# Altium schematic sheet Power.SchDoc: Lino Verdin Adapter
size A3; Organization: Toradex AG; Address1: Ebenaustrasse 10; Address2: Horw; Address3: 6048; Address4: Switzerland; DocumentNumber: 3; Revision: V1.1; SheetNumber: 3; SheetTotal: 8; PageSetup: Record=PageOptions¦CenterHorizontal=True¦CenterVertical=True¦PrintScale=0.73¦XCorrection=1.00¦YCorrection=1.00¦PrintKind=0¦BorderSize=5000000¦LeftOffset=0¦BottomOffset=0¦Orientation=2¦PaperLength=1000¦PaperWidth=1000¦Scale=100¦PaperSource=7¦PrintQuality=-4¦MediaType=1¦DitherType=10¦PaperKind=A4¦PrintScaleMode=1
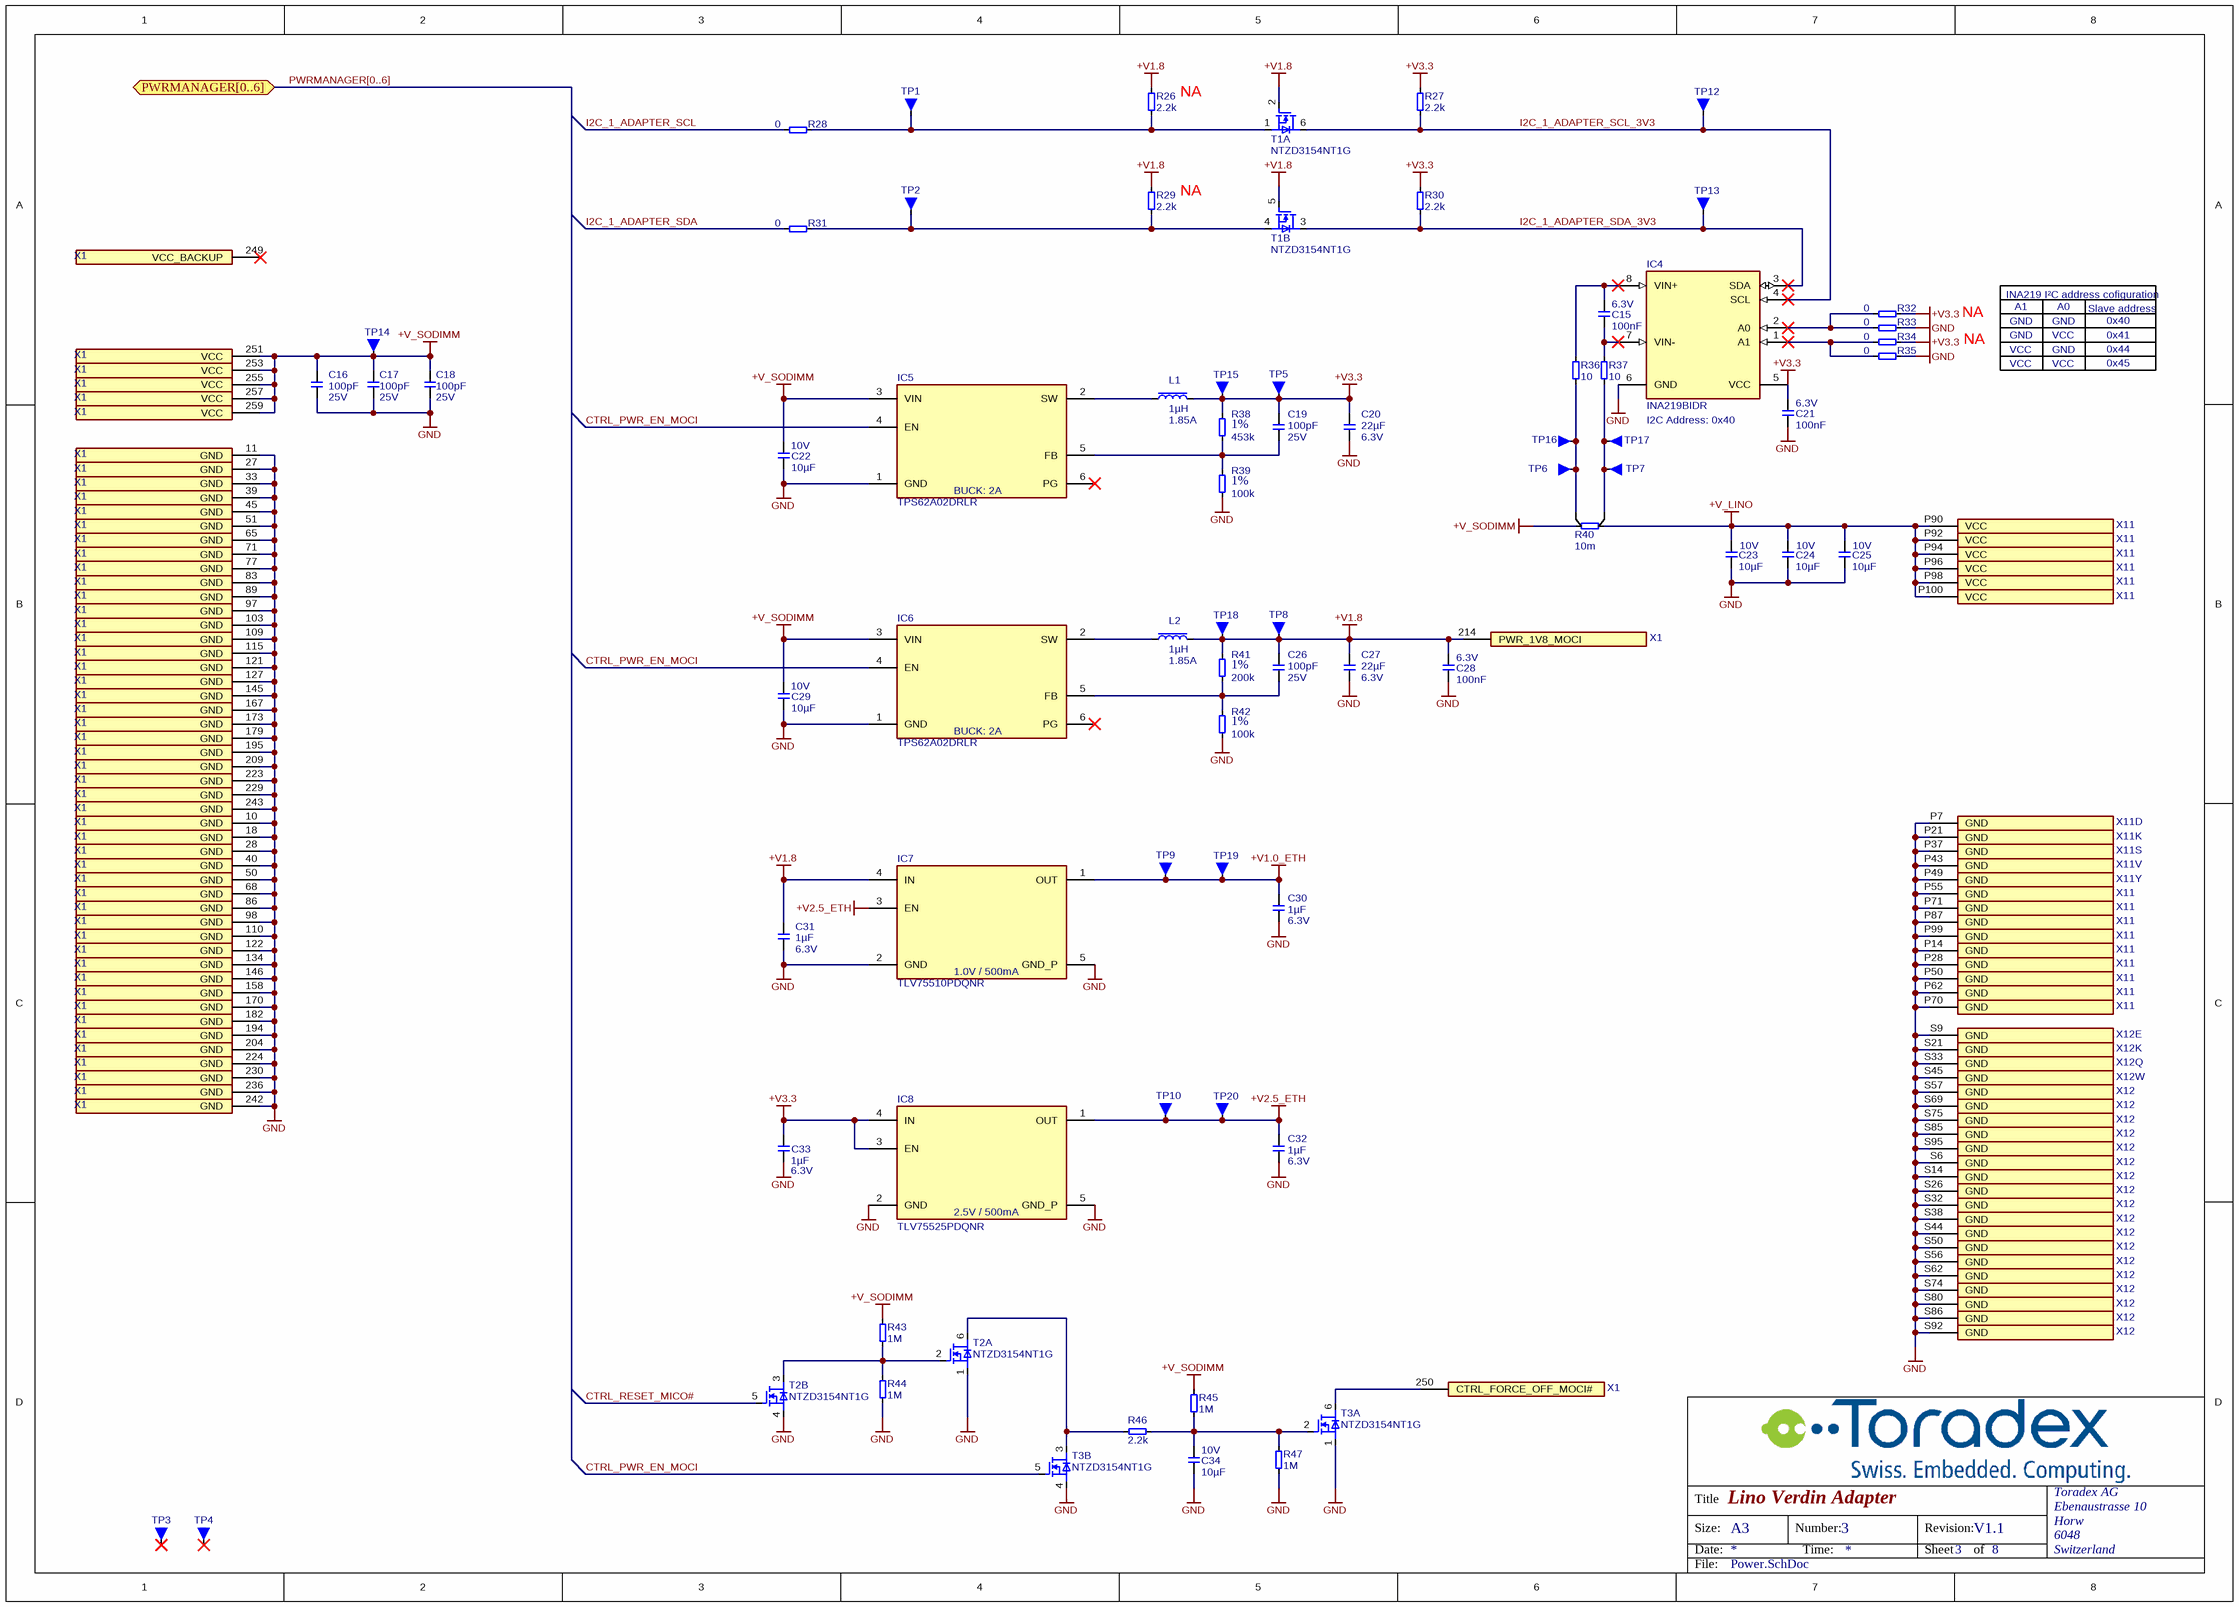
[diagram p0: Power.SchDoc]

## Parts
C15  value 100nF  Rating: 6.3V  [CAPC60X30X33L15L]  (hidden comment: C-X5R-100n-6.3V-10%-0201)
C16  value 100pF  Rating: 25V  [CAPC60X30X33L15L]  (hidden comment: C-NP0-100p-25V-5%-0201)
C17  value 100pF  Rating: 25V  [CAPC60X30X33L15L]  (hidden comment: C-NP0-100p-25V-5%-0201)
C18  value 100pF  Rating: 25V  [CAPC60X30X33L15L]  (hidden comment: C-NP0-100p-25V-5%-0201)
C19  value 100pF  Rating: 25V  [CAPC60X30X33L15L]  (hidden comment: C-NP0-100p-25V-5%-0201)
C20  value 22µF  Rating: 6.3V  [CAPC200X125X100L50N]  (hidden comment: C-X5R-22u-6.3V-20%-0805)
C21  value 100nF  Rating: 6.3V  [CAPC60X30X33L15L]  (hidden comment: C-X5R-100n-6.3V-10%-0201)
C22  value 10µF  Rating: 10V  [CAPC160X80X90L35N]  (hidden comment: C-X5R-10u-10V-20%-0603)
C23  value 10µF  Rating: 10V  [CAPC160X80X90L35N]  (hidden comment: C-X5R-10u-10V-20%-0603)
C24  value 10µF  Rating: 10V  [CAPC160X80X90L35N]  (hidden comment: C-X5R-10u-10V-20%-0603)
C25  value 10µF  Rating: 10V  [CAPC160X80X90L35N]  (hidden comment: C-X5R-10u-10V-20%-0603)
C26  value 100pF  Rating: 25V  [CAPC60X30X33L15L]  (hidden comment: C-NP0-100p-25V-5%-0201)
C27  value 22µF  Rating: 6.3V  [CAPC200X125X100L50N]  (hidden comment: C-X5R-22u-6.3V-20%-0805)
C28  value 100nF  Rating: 6.3V  [CAPC60X30X33L15L]  (hidden comment: C-X5R-100n-6.3V-10%-0201)
C29  value 10µF  Rating: 10V  [CAPC160X80X90L35N]  (hidden comment: C-X5R-10u-10V-20%-0603)
C30  value 1µF  Rating: 6.3V  [CAPC60X30X33L15L]  (hidden comment: C-X5R-1u-6.3V-20%-0201)
C31  value 1µF  Rating: 6.3V  [CAPC60X30X33L15L]  (hidden comment: C-X5R-1u-6.3V-20%-0201)
C32  value 1µF  Rating: 6.3V  [CAPC60X30X33L15L]  (hidden comment: C-X5R-1u-6.3V-20%-0201)
C33  value 1µF  Rating: 6.3V  [CAPC60X30X33L15L]  (hidden comment: C-X5R-1u-6.3V-20%-0201)
C34  value 10µF  Rating: 10V  [CAPC160X80X90L35N]  (hidden comment: C-X5R-10u-10V-20%-0603)
IC4  Manufacturer Part No.: INA219BIDR  [SOIC8P127_500X600X175L100X40_no_Silkscreen]  (hidden comment: IC-TI-INA219BIDR)
IC5  Manufacturer Part No.: TPS62A02DRLR  [SOT563-6P50_160X60L30N]  (hidden comment: TI-TPS62A02DRLR)
IC6  Manufacturer Part No.: TPS62A02DRLR  [SOT563-6P50_160X60L30N]  (hidden comment: TI-TPS62A02DRLR)
IC7  Manufacturer Part No.: TLV75510PDQNR  [X2SON4P65_100X100X40L36X21T48X48-1x1mm]  (hidden comment: IC-TI-TLV75510PDQNR)
IC8  Manufacturer Part No.: TLV75525PDQNR  [X2SON4P65_100X100X40L36X21T48X48-1x1mm]  (hidden comment: TI-TLV75525PDQNR)
L1  value 1µH  Rating: 1.85A  [INDC1008X40N]  (hidden comment: L-TAYIO-MBMK2520T1R0M)
L2  value 1µH  Rating: 1.85A  [INDC1008X40N]  (hidden comment: L-TAYIO-MBMK2520T1R0M)
R26  value 2.2k  [RESC60X30X33L15L]  (hidden comment: R-2.2K-50mW-5%-0201)
R27  value 2.2k  [RESC60X30X33L15L]  (hidden comment: R-2.2K-50mW-5%-0201)
R28  value 0  [RESC60X30X33L15L]  (hidden comment: R-0R-50mW-5%-0201)
R29  value 2.2k  [RESC60X30X33L15L]  (hidden comment: R-2.2K-50mW-5%-0201)
R30  value 2.2k  [RESC60X30X33L15L]  (hidden comment: R-2.2K-50mW-5%-0201)
R31  value 0  [RESC60X30X33L15L]  (hidden comment: R-0R-50mW-5%-0201)
R32  value 0  [RESC60X30X33L15L]  (hidden comment: R-0R-50mW-5%-0201)
R33  value 0  [RESC60X30X33L15L]  (hidden comment: R-0R-50mW-5%-0201)
R34  value 0  [RESC60X30X33L15L]  (hidden comment: R-0R-50mW-5%-0201)
R35  value 0  [RESC60X30X33L15L]  (hidden comment: R-0R-50mW-5%-0201)
R36  value 10  [RESC60X30X33L15L]  (hidden comment: R-10R-50mW-5%-0201)
R37  value 10  [RESC60X30X33L15L]  (hidden comment: R-10R-50mW-5%-0201)
R38  value 453k  Tolerance: 1%  [RESC60X30X33L15L]  (hidden comment: R-453K-50mW-1%-0201)
R39  value 100k  Tolerance: 1%  [RESC60X30X33L15L]  (hidden comment: R-100K-50mW-1%-0201)
R40  value 10m  [RESSC320X160X65L60N]  (hidden comment: R-VISHAY-WSK1206R0100FEA18)
R41  value 200k  Tolerance: 1%  [RESC60X30X33L15L]  (hidden comment: R-200K-50mW-1%-0201)
R42  value 100k  Tolerance: 1%  [RESC60X30X33L15L]  (hidden comment: R-100K-50mW-1%-0201)
R43  value 1M  [RESC60X30X33L15L]  (hidden comment: R-1M-50mW-5%-0201)
R44  value 1M  [RESC60X30X33L15L]  (hidden comment: R-1M-50mW-5%-0201)
R45  value 1M  [RESC60X30X33L15L]  (hidden comment: R-1M-50mW-5%-0201)
R46  value 2.2k  [RESC60X30X33L15L]  (hidden comment: R-2.2K-50mW-5%-0201)
R47  value 1M  [RESC60X30X33L15L]  (hidden comment: R-1M-50mW-5%-0201)
T1  Manufacturer Part No.: NTZD3154NT1G  [SOT563-6P50_160X60L30N]  (hidden comment: T-ONSEMI-NTZD3154NT1G)  (parts A,B of 2)
T2  Manufacturer Part No.: NTZD3154NT1G  [SOT563-6P50_160X60L30N]  (hidden comment: T-ONSEMI-NTZD3154NT1G)  (parts A,B of 2)
T3  Manufacturer Part No.: NTZD3154NT1G  [SOT563-6P50_160X60L30N]  (hidden comment: T-ONSEMI-NTZD3154NT1G)  (parts A,B of 2)
TP1  #TestPin_SMD-1.5x2.2mm#_NoPaste  [TESTPIN/2.20x1.50]  (value not drawn)  (no BOM)
TP2  #TestPin_SMD-1.5x2.2mm#_NoPaste  [TESTPIN/2.20x1.50]  (value not drawn)  (no BOM)
TP3  #TestPin_SMD-1.5x2.2mm#_NoPaste  [TESTPIN/2.20x1.50]  (value not drawn)  (no BOM)
TP4  #TestPin_SMD-1.5x2.2mm#_NoPaste  [TESTPIN/2.20x1.50]  (value not drawn)  (no BOM)
TP5  #TestPin_SMD-1.5x2.2mm#_NoPaste  [TESTPIN/2.20x1.50]  (value not drawn)  (no BOM)
TP6  #TestPin_SMD-1.5x2.2mm#_NoPaste  [TESTPIN/2.20x1.50]  (value not drawn)  (no BOM)
TP7  #TestPin_SMD-1.5x2.2mm#_NoPaste  [TESTPIN/2.20x1.50]  (value not drawn)  (no BOM)
TP8  #TestPin_SMD-1.5x2.2mm#_NoPaste  [TESTPIN/2.20x1.50]  (value not drawn)  (no BOM)
TP9  #TestPin_SMD-1.5x2.2mm#_NoPaste  [TESTPIN/2.20x1.50]  (value not drawn)  (no BOM)
TP10  #TestPin_SMD-1.5x2.2mm#_NoPaste  [TESTPIN/2.20x1.50]  (value not drawn)  (no BOM)
TP12  #TestPin_SMD-1.00mm#_NoPaste  [Pad_SMT_1.0x1.0_NoPaste]  (value not drawn)  (no BOM)
TP13  #TestPin_SMD-1.00mm#_NoPaste  [Pad_SMT_1.0x1.0_NoPaste]  (value not drawn)  (no BOM)
TP14  #TestPin_SMD-1.00mm#_NoPaste  [Pad_SMT_1.0x1.0_NoPaste]  (value not drawn)  (no BOM)
TP15  #TestPin_SMD-1.00mm#_NoPaste  [Pad_SMT_1.0x1.0_NoPaste]  (value not drawn)  (no BOM)
TP16  #TestPin_SMD-1.00mm#_NoPaste  [Pad_SMT_1.0x1.0_NoPaste]  (value not drawn)  (no BOM)
TP17  #TestPin_SMD-1.00mm#_NoPaste  [Pad_SMT_1.0x1.0_NoPaste]  (value not drawn)  (no BOM)
TP18  #TestPin_SMD-1.00mm#_NoPaste  [Pad_SMT_1.0x1.0_NoPaste]  (value not drawn)  (no BOM)
TP19  #TestPin_SMD-1.00mm#_NoPaste  [Pad_SMT_1.0x1.0_NoPaste]  (value not drawn)  (no BOM)
TP20  #TestPin_SMD-1.00mm#_NoPaste  [Pad_SMT_1.0x1.0_NoPaste]  (value not drawn)  (no BOM)
X1  CON-SODIMM-DDR4-TEST  [SODIMM_DDR4_no_Module]  (value not drawn)  (parts C,L,O,R,Z,31,39,42,45,48,51,57,60,63,66,69,73,76,81,84,87,96,106,109,112,120,127,133,136,143,146,147,148,149,150,151,156,159,164,170,175,183,192,198,204,209,215,221,227,233,238,244,249,254,259 of 260)  (no BOM)
X11  CON-LINO-P-CARRIER  [HIROSE_DF40C_100DS_LINO_CARRIER_PRIMARY]  (value not drawn)  (parts D,K,S,V,Y,28,36,44,50,57,64,75,81,85,95,96,97,98,99,100 of 100)
X12  CON-LINO-S-CARRIER  [HIROSE_DF40C_100DS_LINO_CARRIER_SECONDARY]  (value not drawn)  (parts E,K,Q,W,29,35,38,43,48,53,57,63,66,69,72,75,78,81,87,90,93,96 of 100)

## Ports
PWRMANAGER[0..6] (bidir)

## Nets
+V1.0_ETH: C30.2 IC7.1(OUT) TP9.1 TP19.1
+V1.8: C26.2 C27.2 C28.2 C31.2 IC7.4(IN) L2.2 R26.2 R29.2 R41.2 T1.2(G) T1.5(G) TP8.1 TP18.1 X1.214(PWR_1V8_MOCI)
+V2.5_ETH: C32.2 IC7.3(EN) IC8.1(OUT) TP10.1 TP20.1
+V3.3: C19.2 C20.2 C21.2 C33.1 IC4.5(VCC) IC8.3(EN) IC8.4(IN) L1.2 R27.2 R30.2 R32.2 R34.2 R38.2 TP5.1 TP15.1
+V_LINO: C23.2 C24.2 C25.2 R40.1 X11.P90(VCC) X11.P92(VCC) X11.P94(VCC) X11.P96(VCC) X11.P98(VCC) X11.P100(VCC)
+V_SODIMM: C16.2 C17.2 C18.2 C22.2 C29.2 IC5.3(VIN) IC6.3(VIN) R40.4 R43.2 R45.2 TP14.1 X1.251(VCC) X1.253(VCC) X1.255(VCC) X1.257(VCC) X1.259(VCC)
GND: C16.1 C17.1 C18.1 C20.1 C21.1 C22.1 C23.1 C24.1 C25.1 C27.1 C28.1 C29.1 C30.1 C31.1 C32.1 C33.2 C34.1 IC4.6(GND) IC5.1(GND) IC6.1(GND) IC7.2(GND) IC7.5(GND_P) IC8.2(GND) IC8.5(GND_P) R33.2 R35.2 R39.1 R42.1 R44.1 R47.1 T2.1(S) T2.4(S) T3.1(S) T3.4(S) X1.10(GND) X1.11(GND) X1.18(GND) X1.27(GND) X1.28(GND) X1.33(GND) X1.39(GND) X1.40(GND) X1.45(GND) X1.50(GND) X1.51(GND) X1.65(GND) X1.68(GND) X1.71(GND) X1.77(GND) X1.83(GND) X1.86(GND) X1.89(GND) X1.97(GND) X1.98(GND) X1.103(GND) X1.109(GND) X1.110(GND) X1.115(GND) X1.121(GND) X1.122(GND) X1.127(GND) X1.134(GND) X1.145(GND) X1.146(GND) X1.158(GND) X1.167(GND) X1.170(GND) X1.173(GND) X1.179(GND) X1.182(GND) X1.194(GND) X1.195(GND) X1.204(GND) X1.209(GND) X1.223(GND) X1.224(GND) X1.229(GND) X1.230(GND) X1.236(GND) X1.242(GND) X1.243(GND) X11.P7(GND) X11.P14(GND) X11.P21(GND) X11.P28(GND) X11.P37(GND) X11.P43(GND) X11.P49(GND) X11.P50(GND) X11.P55(GND) X11.P62(GND) X11.P70(GND) X11.P71(GND) X11.P87(GND) X11.P99(GND) X12.S6(GND) X12.S9(GND) X12.S14(GND) X12.S21(GND) X12.S26(GND) X12.S32(GND) X12.S33(GND) X12.S38(GND) X12.S44(GND) X12.S45(GND) X12.S50(GND) X12.S56(GND) X12.S57(GND) X12.S62(GND) X12.S69(GND) X12.S74(GND) X12.S75(GND) X12.S80(GND) X12.S85(GND) X12.S86(GND) X12.S92(GND) X12.S95(GND)
CTRL_PWR_EN_MOCI: IC5.4(EN) IC6.4(EN) T3.5(G)
CTRL_RESET_MICO#: T2.5(G)
I2C_1_ADAPTER_SCL: R28.1
I2C_1_ADAPTER_SCL_3V3: IC4.4(SCL) R27.1 T1.6(D) TP12.1
I2C_1_ADAPTER_SDA: R31.1
I2C_1_ADAPTER_SDA_3V3: IC4.3(SDA) R30.1 T1.3(D) TP13.1
NetC15_1: C15.1 IC4.7(VIN-) R37.2
NetC15_2: C15.2 IC4.8(VIN+) R36.2
NetC19_1: C19.1 IC5.5(FB) R38.1 R39.2
NetC26_1: C26.1 IC6.5(FB) R41.1 R42.2
NetC34_2: C34.2 R45.1 R46.1 R47.2 T3.2(G)
NetIC4_1: IC4.1(A1) R34.1 R35.1
NetIC4_2: IC4.2(A0) R32.1 R33.1
NetIC5_2: IC5.2(SW) L1.1
NetIC6_2: IC6.2(SW) L2.1
NetR26_1: R26.1 R28.2 T1.1(S) TP1.1
NetR29_1: R29.1 R31.2 T1.4(S) TP2.1
NetR36_1: R36.1 R40.3 TP6.1 TP16.1
NetR37_1: R37.1 R40.2 TP7.1 TP17.1
NetR43_1: R43.1 R44.2 T2.2(G) T2.3(D)
NetR46_2: R46.2 T2.6(D) T3.3(D)
NetT3_6: T3.6(D) X1.250(CTRL_FORCE_OFF_MOCI#)

Not connected (* = marked no-connect by the designer): IC5 6(PG)*; IC6 6(PG)*; TP3 1*; TP4 1*; X1 249(VCC_BACKUP)*

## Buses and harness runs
bus PWRMANAGER[0..6] = port PWRMANAGER[0..6]

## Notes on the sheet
- (near R26) NA
- (near R29) NA
- NA
- INA219 I²C address cofiguration
- GND
- A1
- VCC
- A0
- Slave address
- 0x40
- 0x41
- 0x44
- 0x45
- I2C Address: 0x40

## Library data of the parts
C15 C21 C28 = CMP-00475-11: Capacitor Ceramic X5R 100nF 6.3V 20% 0201; Manufacturer Name: Generic; Tolerance: 10%
C16-C19 C26 = CMP-00463-10: Capacitor Ceramic NP0 100pF 25V 5% 0201; Manufacturer Name: Generic
C20 C27 = CMP-00470-9: Capacitor Ceramic X5R 22uF 6.3V 20% 0805; Manufacturer Name: Generic
C22-C25 C29 C34 = CMP-00250-13: Capacitor Ceramic X5R 10uF 10V 20% 0603; Manufacturer Name: Generic
C30-C33 = CMP-00466-9: Capacitor Ceramic X5R 1uF 6.3V 20% 0201; Manufacturer Name: Generic
IC4 = CMP-00192-8: CURRENT/POWER MONITOR with I2C Interface; Manufacturer Name: Texas Instruments
IC5 IC6 = CMP-00563-7: Integrated Buck Regulator 2A; Manufacturer Name: Texas Instruments
IC7 = CMP-00508-6: LDO / Linear Voltage Regulator (Vout=1.0V, Iout=500mA(max), Vin(max)=5.5V), X2SON, -40C to +85C; Manufacturer Name: Texas Instruments
IC8 = CMP-00571-5: LDO / Linear Voltage Regulator (Vout=2.5V, Iout=500mA(max), Vin(max)=5.5V), X2SON, -40C to +85C; Manufacturer Name: Texas Instruments
L1 L2 = CMP-00421-8: Inductor 1uH, 20%, Irms=1.85A, DCR= 60mOhm, 1008 (2520 metric); Manufacturer Name: Taiyo Yuden; DC Resistance: 60m
R26 R27 R29 R30 R46 = CMP-00441-14: Resistor 2.2K ohm 50mW 5% 0201; Manufacturer Name: Generic
R28 R31-R35 = CMP-00402-19: Resistor 0 ohm 50mW 5% 0201; Manufacturer Name: Generic
R36 R37 = CMP-00428-14: Resistor 10 ohm 50mW 5% 0201; Manufacturer Name: Generic
R38 = CMP-00445-14: Resistor 453K ohm 50mW 1% 0201; Manufacturer Name: Generic
R39 R42 = CMP-00436-14: Resistor 100K ohm 50mW 1% 0201; Manufacturer Name: Generic
R40 = CMP-00325-8: 10 mOhms ±1% 0.5W,Chip Resistor 1206 (3216 Metric) Current Sense, Moisture Resistant, Pulse Withstanding Metal Element; Manufacturer Name: Vishay; Rating: 500mW
R41 = CMP-00827-2: Resistor 200K ohm 50mW 1% 0201; Manufacturer Name: Generic
R43-R45 R47 = CMP-00425-14: Resistor 1M ohm 50mW 5% 0201; Manufacturer Name: Generic
T1-T3 = CMP-00121-16: Dual N-Channel 20V (D-S)  MOSFET, 20 V, 540 mA, SOT−563; Manufacturer Name: onsemi; Drain Current-Max (ID): 540mA; Transistor Type: 2N; Drain-source On Resistance-Max: 0.55
TP1-TP10 = CMP-00568-6: Testpin 1.5x2.2mm; Manufacturer Name: Generic
TP12-TP20 = CMP-00567-9: Testpin Square 1.0mm; Manufacturer Name: Generic
X1 = CMP-00731-8: DDR4 SODIMM Card Edge, 260 pins, 0.5mm Pitch; Manufacturer Name: Generic; Manufacturer Part No.: No Physical Component; Gender: Male
X11 = CMP-00961-5: LINO Primary Connector Carrier; Manufacturer Name: Amphenol; Manufacturer Part No.: 10164227-1001A1RLF; Rows: 2
X12 = CMP-00962-5: LINO Secondary Connector; Manufacturer Part No.: 10164227-1001A1RLF; Manufacturer Name: Amphenol; Rows: 2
